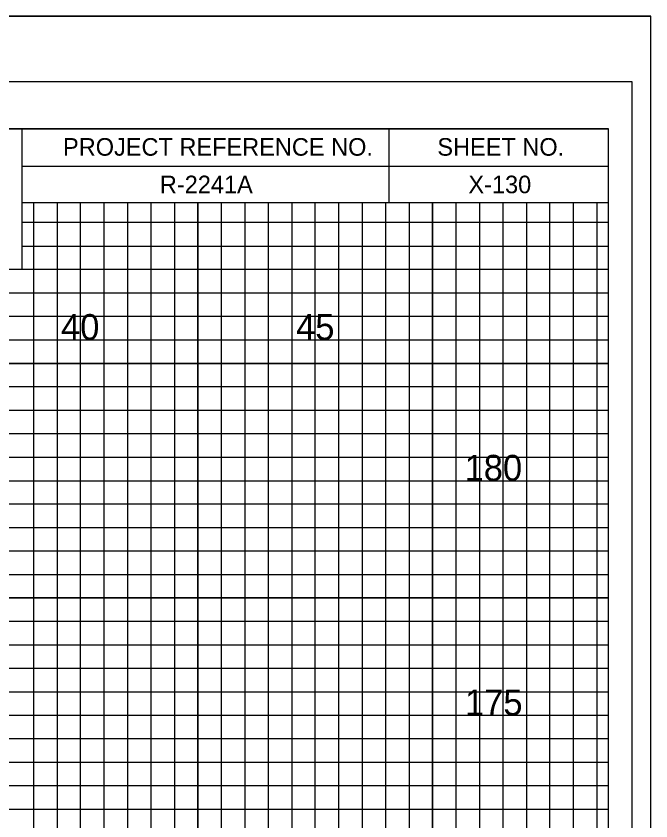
# Model space of a CAD drawing. Extents: x -4 to 103, y -2 to 209.
# Drawn here: x 89.88 to 103.4, y 121.08 to 138.22 of the extents above; entities that cross this region are included whole.
import ezdxf

# ---------------------------------------------------------------- set-up
doc = ezdxf.new("R2010")
doc.units = 0
for name, color, linetype in [('Prop XS Elevation Labels', 7, 'Continuous'), ('Prop XS Offset Labels', 7, 'Continuous'), ('Prop XS Project Number', 7, 'Continuous'), ('Prop XS Sheet Number', 7, 'Continuous'), ('Sheet Cross Section CELL', 7, 'Continuous'), ('Sheet Cross Section Grid Major CELL', 7, 'Continuous'), ('Sheet Cross Section Grid Middle CELL', 7, 'Continuous'), ('Sheet Cutting Line CELL', 7, 'Continuous'), ('Sheet DOT Grid CELL', 7, 'Continuous'), ('Sheet Plot Border Inside CELL', 7, 'Continuous'), ('Sheet Plot Border Outside CELL', 7, 'Continuous')]:
    doc.layers.add(name, color=color, linetype=linetype)

msp = doc.modelspace()

# ---------------------------------------------------------------- linework, layer by layer
at = {"layer": 'Sheet Cross Section CELL'}
for p, q in [((90, 135.825), (102.5, 135.825)), ((90, 135.825), (102.5, 135.825)), ((97.825, 134.25), (97.825, 135.825)), ((101.875, 135.825), (101.875, 135.825)), ((102.5, 135.825), (102.5, 135.825)), ((102.5, 134.25), (102.5, 135.825)), ((102.5, 135.825), (102.5, 135.825)), ((102.5, 135.825), (102.5, 135.825)), ((102.5, 134.25), (102.5, 135.825)), ((90, 135.025), (102.5, 135.025)), ((90, 134.25), (102.5, 134.25)), ((99.4, 134.25), (99.4, 134.25)), ((99.4, 134.25), (99.4, 134.25))]:
    msp.add_line(p, q, dxfattribs=at)
for points in [[(102.5, 135.825), (0, 135.825), (0, 70.825), (102.5, 70.825)], [(83.75, 135.825), (90, 135.825), (90, 132.825), (83.75, 132.825)]]:
    msp.add_lwpolyline(points, close=True, dxfattribs=at)
at = {"layer": 'Sheet Cross Section Grid Major CELL'}
for points in [[(91.25, 70.825), (91.25, 134.25), (93.75, 134.25), (93.75, 70.825)], [(96.25, 70.825), (96.25, 134.25), (98.75, 134.25), (98.75, 70.825)], [(101.25, 70.825), (101.25, 134.25)], [(90, 133.325), (102.5, 133.325)], [(0, 128.325), (102.5, 128.325), (102.5, 130.825), (0, 130.825)], [(0, 123.325), (102.5, 123.325), (102.5, 125.825), (0, 125.825)]]:
    msp.add_lwpolyline(points, dxfattribs=at)
at = {"layer": 'Sheet Cross Section Grid Middle CELL'}
for points in [[(90.25, 70.825), (90.25, 134.25), (90.75, 134.25), (90.75, 70.825)], [(91.75, 70.825), (91.75, 134.25), (92.25, 134.25), (92.25, 70.825)], [(92.75, 70.825), (92.75, 134.25), (93.25, 134.25), (93.25, 70.825)], [(94.25, 70.825), (94.25, 134.25), (94.75, 134.25), (94.75, 70.825)], [(95.25, 70.825), (95.25, 134.25), (95.75, 134.25), (95.75, 70.825)], [(96.75, 70.825), (96.75, 134.25), (97.25, 134.25), (97.25, 70.825)], [(97.75, 70.825), (97.75, 134.25), (98.25, 134.25), (98.25, 70.825)], [(99.25, 70.825), (99.25, 134.25), (99.75, 134.25), (99.75, 70.825)], [(100.25, 70.825), (100.25, 134.25)], [(100.25, 134.25), (100.75, 134.25), (100.75, 70.825), (101.75, 70.825), (101.75, 134.25), (102.25, 134.25), (102.25, 70.825)], [(102.5, 132.825), (102.5, 133.825), (90, 133.825)], [(0, 132.325), (102.5, 132.325), (102.5, 132.825), (0, 132.825)], [(0, 131.325), (102.5, 131.325), (102.5, 131.825), (0, 131.825)], [(0, 129.825), (102.5, 129.825), (102.5, 130.325), (0, 130.325)], [(0, 128.825), (102.5, 128.825), (102.5, 129.325), (0, 129.325)], [(0, 127.325), (102.5, 127.325), (102.5, 127.825), (0, 127.825)], [(0, 126.325), (102.5, 126.325), (102.5, 126.825), (0, 126.825)], [(0, 124.825), (102.5, 124.825), (102.5, 125.325), (0, 125.325)], [(0, 123.825), (102.5, 123.825), (102.5, 124.325), (0, 124.325)], [(0, 122.325), (102.5, 122.325), (102.5, 122.825), (0, 122.825)], [(0, 121.325), (102.5, 121.325), (102.5, 121.825), (0, 121.825)]]:
    msp.add_lwpolyline(points, dxfattribs=at)
at = {"layer": 'Sheet Cutting Line CELL'}
msp.add_line((-3.5, 138.225), (103.4, 138.225), dxfattribs=at)
at = {"layer": 'Sheet DOT Grid CELL'}
for p, q in [((91.25, 70.825), (91.25, 134.25)), ((93.75, 70.825), (93.75, 134.25)), ((96.25, 70.825), (96.25, 134.25)), ((98.75, 70.825), (98.75, 134.25)), ((101.25, 70.825), (101.25, 134.25)), ((90, 133.325), (102.5, 133.325)), ((0, 130.825), (102.5, 130.825)), ((0, 128.325), (102.5, 128.325)), ((0, 125.825), (102.5, 125.825)), ((0, 123.325), (102.5, 123.325))]:
    msp.add_line(p, q, dxfattribs=at)
at = {"layer": 'Sheet Plot Border Inside CELL'}
msp.add_lwpolyline([(103, 136.825), (-2.8, 136.825), (-2.8, 69.825), (103, 69.825)], close=True, dxfattribs=at)
at = {"layer": 'Sheet Plot Border Outside CELL'}
msp.add_lwpolyline([(103.4, 138.225), (-3.5, 138.225), (-3.5, 68.4), (103.4, 68.4)], close=True, dxfattribs=at)

# ---------------------------------------------------------------- texts
at = {"layer": 'Prop XS Elevation Labels'}
for s, p in [('180', (99.42958, 128.325)), ('175', (99.43825, 123.325))]:
    msp.add_text(s, height=0.55, dxfattribs=at).set_placement(p)
at = {"layer": 'Prop XS Offset Labels'}
for s, p in [('40', (90.83125, 131.325)), ('45', (95.83992, 131.325))]:
    msp.add_text(s, height=0.55, dxfattribs=at).set_placement(p)
at = {"layer": 'Prop XS Project Number'}
msp.add_text('R-2241A', height=0.375, dxfattribs=at).set_placement((92.93778, 134.45))
at = {"layer": 'Prop XS Sheet Number'}
msp.add_text('X-130', height=0.375, dxfattribs=at).set_placement((99.51205, 134.45))
at = {"layer": 'Sheet Cross Section CELL'}
for s, p in [('PROJECT REFERENCE NO.', (90.875, 135.25)), ('SHEET NO.', (98.85, 135.25))]:
    msp.add_text(s, height=0.375, dxfattribs=at).set_placement(p)

doc.saveas('drawing.dxf')
